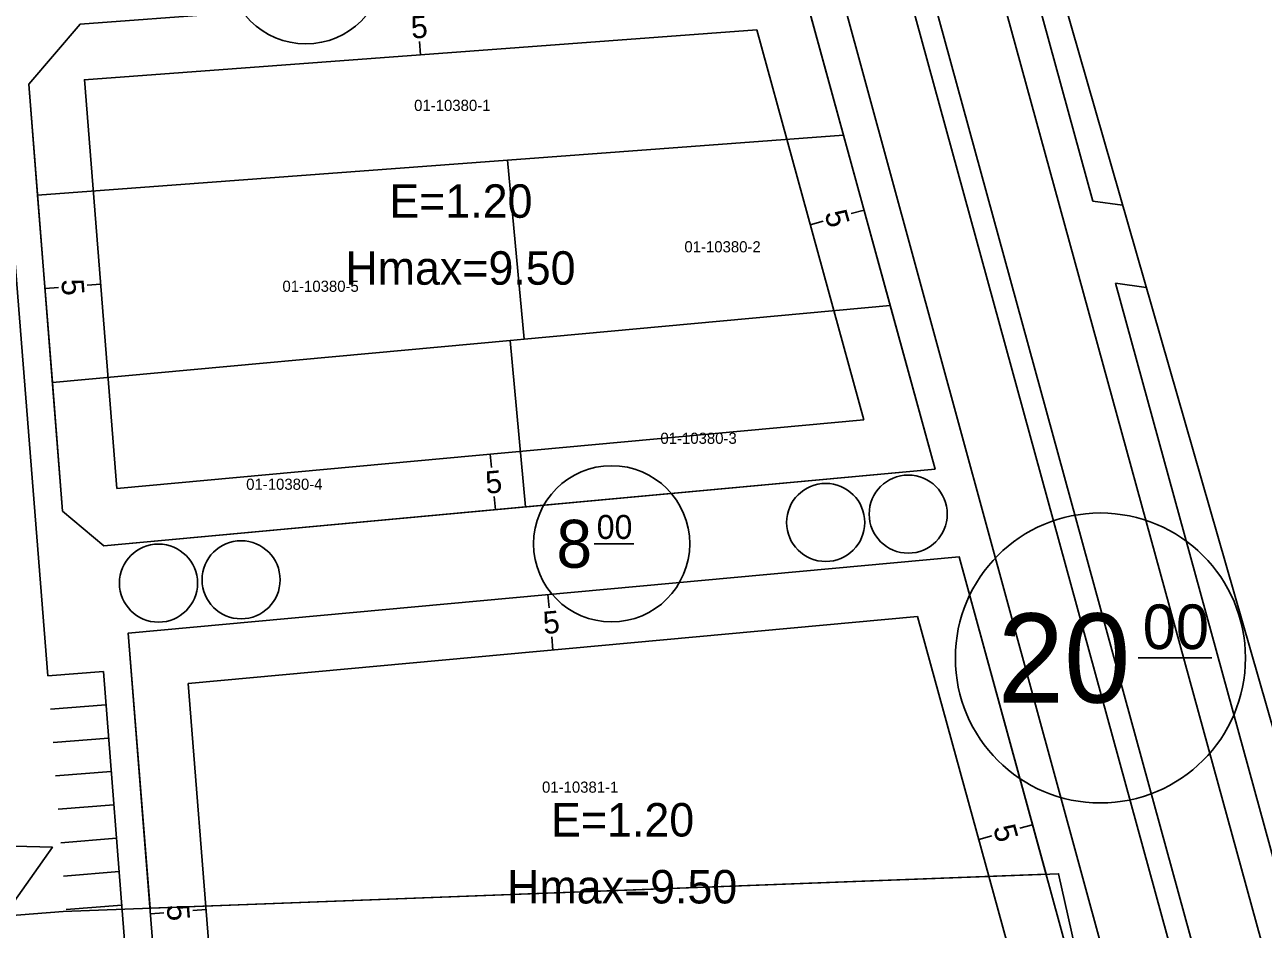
# Model space of a CAD drawing. Extents: x 419396 to 421519, y 4453567 to 4456767.
# Drawn here: x 421314.2 to 421425.2, y 4454908.3 to 4454989.4 of the extents above; entities that cross this region are included whole.
import ezdxf

# ---------------------------------------------------------------- set-up
doc = ezdxf.new("R2010")
doc.units = 0
for name, color, linetype in [('0_KADASTRO', 7, 'Continuous'), ('Level 20', 7, 'Continuous'), ('Level 28', 7, 'Continuous'), ('Level 29', 7, 'Continuous'), ('Level 30', 7, 'Continuous'), ('Level 55', 7, 'Continuous'), ('Level 58', 7, 'Continuous'), ('Level 62', 7, 'Continuous'), ('Level 9', 7, 'Continuous')]:
    doc.layers.add(name, color=color, linetype=linetype)

msp = doc.modelspace()

# ---------------------------------------------------------------- linework, layer by layer
at = {"layer": '0_KADASTRO'}
for points in [[(421385.14, 4454988.41), (421383.54, 4454994.24), (421319.18, 4454989.43), (421314.59, 4454984.07), (421315.37, 4454974.11), (421357.48, 4454977.25), (421387.58, 4454979.5)], [(421385.14, 4454988.41), (421383.54, 4454994.24), (421319.18, 4454989.43), (421314.59, 4454984.07), (421315.37, 4454974.11), (421357.48, 4454977.25), (421387.58, 4454979.5)], [(421358.96, 4454961.2), (421391.77, 4454964.22), (421387.58, 4454979.5), (421357.48, 4454977.25)], [(421358.96, 4454961.2), (421391.77, 4454964.22), (421387.58, 4454979.5), (421357.48, 4454977.25)], [(421357.48, 4454977.25), (421315.37, 4454974.11), (421316.7, 4454957.31), (421357.71, 4454961.09), (421358.96, 4454961.2)], [(421357.48, 4454977.25), (421315.37, 4454974.11), (421316.7, 4454957.31), (421357.71, 4454961.09), (421358.96, 4454961.2)], [(421357.71, 4454961.09), (421359.09, 4454946.15), (421395.8, 4454949.53), (421391.77, 4454964.22), (421358.96, 4454961.2)], [(421357.71, 4454961.09), (421359.09, 4454946.15), (421395.8, 4454949.53), (421391.77, 4454964.22), (421358.96, 4454961.2)], [(421316.7, 4454957.31), (421317.61, 4454945.78), (421321.3, 4454942.67), (421359.09, 4454946.15), (421357.71, 4454961.09)], [(421316.7, 4454957.31), (421317.61, 4454945.78), (421321.3, 4454942.67), (421359.09, 4454946.15), (421357.71, 4454961.09)], [(421405.75, 4454913.23), (421397.94, 4454941.69), (421323.49, 4454934.84), (421325.44, 4454910.18)], [(421405.75, 4454913.23), (421397.94, 4454941.69), (421323.49, 4454934.84), (421325.44, 4454910.18)], [(421137.98, 4454923.3), (421214.86, 4454919.45), (421262.85, 4454917.05), (421316.7, 4454915.64), (421312.35, 4454909.46), (421306.52, 4454893.75), (421298.93, 4454879.53), (421285.07, 4454880), (421282.36, 4454831.02), (421298.78, 4454830.11), (421298.12, 4454819), (421220.47, 4454824.89), (421221.51, 4454877.03), (421221.57, 4454879.85), (421203.67, 4454880.3), (421204.77, 4454912.41), (421155.31, 4454914.55), (421152.21, 4454911.69), (421151.19, 4454881.63), (421145.39, 4454881.78), (421142.95, 4454883.52), (421140.69, 4454887.48), (421139.91, 4454900.08)], [(421297.61, 4454855.78), (421298.02, 4454877.83), (421306.52, 4454893.75), (421312.35, 4454909.46), (421317.66, 4454909.88), (421406.86, 4454913.27), (421417.65, 4454865.27)], [(421297.61, 4454855.78), (421298.02, 4454877.83), (421306.52, 4454893.75), (421312.35, 4454909.46), (421317.66, 4454909.88), (421406.86, 4454913.27), (421417.65, 4454865.27)]]:
    msp.add_lwpolyline(points, close=True, dxfattribs=at)
at = {"layer": 'Level 20'}
for p, q in [((421319.55, 4454984.44), (421379.81, 4454988.94)), ((421379.81, 4454988.94), (421389.4, 4454953.96)), ((421349.68, 4454986.69), (421349.59, 4454987.89)), ((421322.47, 4454947.8), (421319.57, 4454984.47)), ((421389.43, 4454972.77), (421388.27, 4454972.46)), ((421384.6, 4454971.45), (421385.76, 4454971.77)), ((421316.04, 4454965.74), (421317.23, 4454965.83)), ((421321.02, 4454966.13), (421319.82, 4454966.04)), ((421389.4, 4454953.96), (421322.47, 4454947.8)), ((421355.93, 4454950.88), (421356.04, 4454949.69)), ((421356.39, 4454945.9), (421356.28, 4454947.1)), ((421361.09, 4454938.3), (421361.2, 4454937.11)), ((421328.87, 4454930.31), (421394.23, 4454936.33)), ((421394.23, 4454936.33), (421405.19, 4454896.34)), ((421361.55, 4454933.32), (421361.44, 4454934.52)), ((421332.07, 4454889.8), (421328.87, 4454930.31)), ((421404.53, 4454917.66), (421403.38, 4454917.34)), ((421399.71, 4454916.34), (421400.87, 4454916.65)), ((421325.48, 4454909.66), (421326.68, 4454909.76)), ((421330.47, 4454910.06), (421329.27, 4454909.96))]:
    msp.add_line(p, q, dxfattribs=at)
at = {"layer": 'Level 28'}
msp.add_line((421321.3, 4454942.67), (421317.61, 4454945.77), dxfattribs=at)
at = {"layer": 'Level 29'}
for p, q in [((421409.94, 4454973.58), (421399.37, 4455012.13)), ((421383.54, 4454994.23), (421395.8, 4454949.53)), ((421314.59, 4454984.07), (421319.18, 4454989.43)), ((421317.61, 4454945.77), (421314.59, 4454984.07)), ((421412.6, 4454973.21), (421409.94, 4454973.58)), ((421441.81, 4454857.3), (421411.95, 4454966.22)), ((421411.96, 4454966.23), (421414.71, 4454965.84)), ((421395.8, 4454949.53), (421321.3, 4454942.67)), ((421323.49, 4454934.84), (421397.94, 4454941.69)), ((421397.94, 4454941.69), (421411.59, 4454891.9)), ((421327.48, 4454884.37), (421323.49, 4454934.84))]:
    msp.add_line(p, q, dxfattribs=at)
at = {"layer": 'Level 55'}
for centre in [(421393.39, 4454945.51), (421385.99, 4454944.76), (421326.2, 4454939.32), (421333.6, 4454939.62)]:
    msp.add_circle(centre, 3.5, dxfattribs=at)
at = {"layer": 'Level 58'}
for p, q in [((421365.25, 4454942.85), (421368.8, 4454942.85)), ((421414, 4454932.61), (421420.6, 4454932.61)), ((421414, 4454932.61), (421420.6, 4454932.61))]:
    msp.add_line(p, q, dxfattribs=at)
for centre, radius in [((421339.41, 4454994.67), 7), ((421366.81, 4454942.85), 7), ((421410.61, 4454932.61), 13), ((421410.61, 4454932.61), 13)]:
    msp.add_circle(centre, radius, dxfattribs=at)
at = {"layer": 'Level 62'}
for p, q in [((421432.06, 4454851.29), (421377.52, 4455050.31)), ((421433.99, 4454851.82), (421379.49, 4455050.65)), ((421439.78, 4454853.41), (421386.03, 4455049.48)), ((421428.12, 4454842.97), (421374.21, 4455040.42)), ((421312.09, 4454983.88), (421316.27, 4454931)), ((421316.27, 4454931), (421321.26, 4454931.4)), ((421321.26, 4454931.4), (421324.8, 4454886.54)), ((421316.51, 4454928.01), (421321.49, 4454928.41)), ((421316.75, 4454925.02), (421321.73, 4454925.42)), ((421316.98, 4454922.03), (421321.97, 4454922.42)), ((421317.22, 4454919.04), (421322.2, 4454919.43)), ((421317.46, 4454916.05), (421322.44, 4454916.44)), ((421317.69, 4454913.06), (421322.68, 4454913.45)), ((421317.93, 4454910.07), (421322.91, 4454910.46))]:
    msp.add_line(p, q, dxfattribs=at)
at = {"layer": 'Level 9'}
msp.add_line((421444.17, 4454863.26), (421391.68, 4455046.06), dxfattribs=at)

# ---------------------------------------------------------------- texts
at = {"layer": '0_KADASTRO'}
for s, p in [('01-10380-1', (421349.11, 4454981.66)), ('01-10380-1', (421349.11, 4454981.66)), ('01-10380-2', (421373.33, 4454968.98)), ('01-10380-2', (421373.33, 4454968.98)), ('01-10380-5', (421337.31, 4454965.44)), ('01-10380-5', (421337.31, 4454965.44)), ('01-10380-3', (421371.18, 4454951.81)), ('01-10380-3', (421371.18, 4454951.81)), ('01-10380-4', (421334.06, 4454947.69)), ('01-10380-4', (421334.06, 4454947.69)), ('01-10381-1', (421360.57, 4454920.53)), ('01-10381-1', (421360.57, 4454920.53))]:
    msp.add_text(s, height=1, dxfattribs=at).set_placement(p)
at = {"layer": 'Level 20'}
for rotation, p in [(4.2685, (421348.9, 4454988.14)), (285.3287, (421385.87, 4454972.49)), (274.5195, (421317.48, 4454966.52)), (5.2589, (421355.59, 4454947.33)), (5.2589, (421360.75, 4454934.75)), (285.3284, (421400.98, 4454917.38)), (274.5195, (421326.93, 4454910.45))]:
    msp.add_text('5', height=2, rotation=rotation, dxfattribs=at).set_placement(p)
at = {"layer": 'Level 30'}
for s, p in [('E=1.20', (421346.89, 4454972.08)), ('Hmax=9.50', (421342.95, 4454966.08)), ('E=1.20', (421361.38, 4454916.6)), ('Hmax=9.50', (421357.44, 4454910.6))]:
    msp.add_text(s, height=3, dxfattribs=at).set_placement(p)
at = {"layer": 'Level 58'}
for s, height, p in [('8', 4.3, (421361.86, 4454940.7)), ('00', 2.152, (421365.47, 4454943.28)), ('00', 3.997, (421414.4, 4454933.41)), ('00', 3.997, (421414.4, 4454933.41)), ('20', 7.993, (421401.41, 4454928.61)), ('20', 7.993, (421401.41, 4454928.61))]:
    msp.add_text(s, height=height, dxfattribs=at).set_placement(p)

doc.saveas('drawing.dxf')
